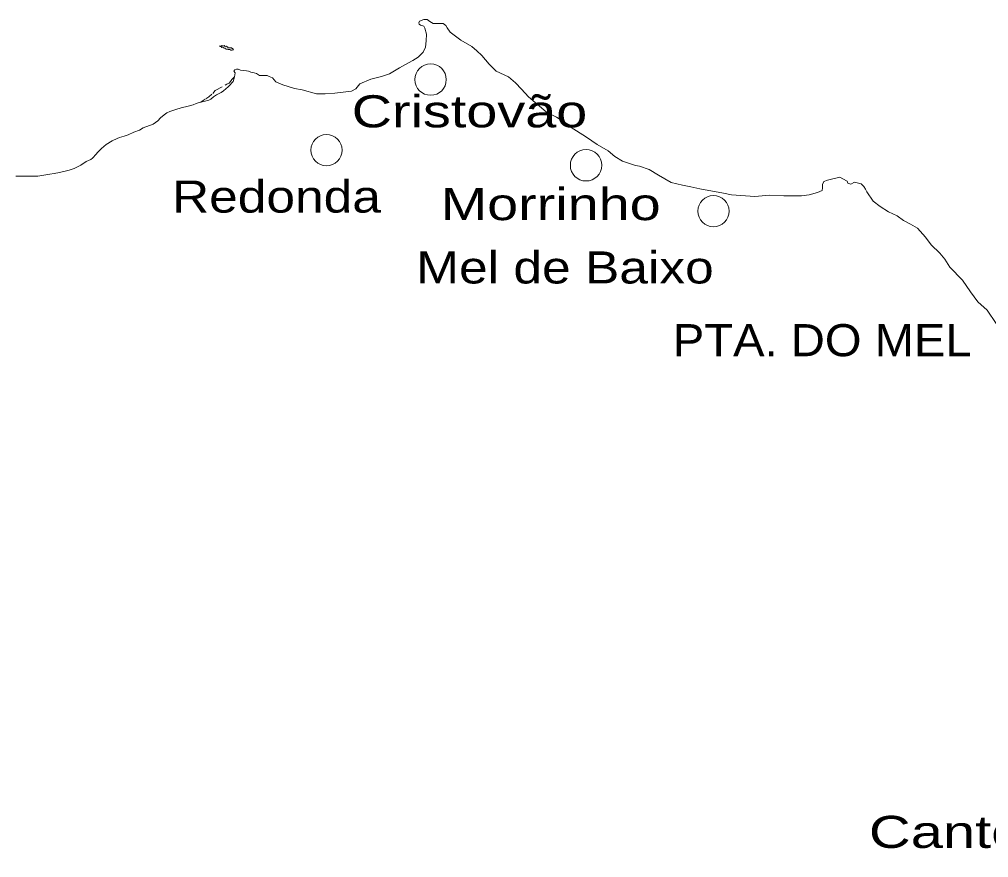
# Model space of a CAD drawing. Extents: x 47169 to 972804, y 7447977 to 9608469.
# Drawn here: x 717313 to 737887, y 9438119 to 9455908 of the extents above; entities that cross this region are included whole.
import ezdxf

# ---------------------------------------------------------------- set-up
doc = ezdxf.new("R2010")
doc.units = 0
doc.header["$LTSCALE"] = 270
doc.linetypes.add('DOTTED', pattern=[1.5, 0.3, -1.2])
doc.layers.add('1', color=7, linetype='Continuous', lineweight=13)
doc.layers.add('2', color=7, linetype='Continuous', lineweight=13)
doc.layers.add('3', color=7, linetype='Continuous')

msp = doc.modelspace()

# ---------------------------------------------------------------- linework, layer by layer
at = {"layer": '1'}
for points in [[(736954.5, 9450817.2), (736852.8, 9450945.9), (736668.1, 9451125.7), (736547.7, 9451287.6), (736376.4, 9451478.4), (736230.2, 9451561.8), (736079.6, 9451639.7), (735946.8, 9451740.8), (735762.9, 9451823.2), (735582.4, 9451936.7), (735434.1, 9452047.8), (735300.5, 9452246.2), (735275.1, 9452301.6), (735240.9, 9452358.1), (735182.3, 9452415.8), (735039.3, 9452450.5), (734963.7, 9452407.6), (734901.7, 9452432.2), (734886.3, 9452475.4), (734874.1, 9452480.9), (734725.7, 9452558.8), (734465.9, 9452498.8), (734392.5, 9452464.8), (734360.2, 9452404), (734360, 9452335.5), (734357.6, 9452276.8), (734256.5, 9452235.1), (734075.5, 9452183.7), (733914.5, 9452164.3), (733729.2, 9452160.5), (733537.3, 9452162.2), (733234.5, 9452178.6), (732921.6, 9452148.7), (732429.1, 9452184.5), (732261.7, 9452221.5), (731759.4, 9452310.5), (731567.6, 9452352), (731391.3, 9452390.2), (731147.4, 9452449.6), (730881.7, 9452605.3), (730684.6, 9452722.1), (730475.1, 9452794.6), (730388.6, 9452803.7), (730116, 9452899.7), (729954.3, 9452995.3), (729809.4, 9453121.9), (729576.8, 9453253.1), (729352.1, 9453409.8), (729139.5, 9453545.4), (729027.7, 9453616.5), (728989, 9453669.8), (728838.4, 9453755.4), (728715.5, 9453831), (728493.9, 9453944.5), (728120, 9454265.3), (727971.8, 9454427.3), (727845.7, 9454561.5), (727697.5, 9454685.8), (727434.9, 9454811.6), (727286.7, 9454960.3), (727127.5, 9455141.1), (727022.4, 9455239.9), (726915.1, 9455333.1), (726682.5, 9455468.8), (726460, 9455635.4), (726393.7, 9455727.4), (726366.2, 9455778.3), (726309.7, 9455818.3), (726189.9, 9455817.6), (726093.4, 9455820.1), (726029.2, 9455862.3), (725967.2, 9455907.9), (725896.2, 9455908.1), (725809.5, 9455871.8), (725789.4, 9455833.2), (725800.4, 9455805.5), (725828.1, 9455785.5), (725896.8, 9455767.6), (725922.2, 9455724.4), (725951.8, 9455594.9), (725951.3, 9455452.2), (725934.3, 9455315.1), (725881.8, 9455210.2), (725775, 9455109.8), (725668.3, 9455038.3), (725492.7, 9454940.4), (725381.6, 9454876.6), (725172.6, 9454755.5), (725002.7, 9454698.5), (724770.7, 9454636.2), (724541.8, 9454537.3), (724458.3, 9454435.8), (724361.7, 9454384.1), (724007.6, 9454338.8), (723806.8, 9454327.2), (723620.4, 9454328.9), (723317.8, 9454416.1), (723153.7, 9454443.1), (722904.3, 9454515.7), (722753.6, 9454581.5), (722682.9, 9454667.9)], [(722413.5, 9454720.7), (722370.3, 9454748.5), (722343.7, 9454761.9), (722298.2, 9454773.1), (722229.5, 9454791), (722175.2, 9454812.2), (722130.8, 9454815.6), (722069.8, 9454822.4), (722007.8, 9454833.7), (721957.9, 9454853.7), (721922.4, 9454854.9), (721885.7, 9454837.4), (721862.3, 9454807.6), (721892.2, 9454775.4), (721877.5, 9454685.8), (721852.8, 9454590.8), (721817.2, 9454552.2), (721794.9, 9454524.6), (721744.9, 9454473.9), (721647, 9454390.1), (721593.6, 9454353.8), (721499.2, 9454307.6), (721436.9, 9454261.3), (721374.7, 9454215.1), (721333.6, 9454193.1), (721231.4, 9454162.4), (721165.9, 9454152.7), (721104.9, 9454137.3), (721067.1, 9454122), (721001.5, 9454092.3), (720922.7, 9454070.4), (720842.8, 9454054.1), (720770.6, 9454035.5), (720610.7, 9453990.6), (720508.6, 9453953.3), (720441.9, 9453922.5), (720387.4, 9453881.8), (720309.6, 9453815.7), (720255.1, 9453756.1), (720155, 9453687.8), (719941.8, 9453603.3), (719864, 9453559.3), (719745.1, 9453516.5), (719624, 9453461.5), (719538.5, 9453429.7), (719438.6, 9453403.5), (719388.6, 9453378.2), (719283.1, 9453327.6), (719154.2, 9453252.8), (719057.4, 9453166.8), (718972.9, 9453085.2), (718942.8, 9453047.7), (718863.8, 9452962.8), (718831.5, 9452934.1), (718731.5, 9452889), (718616, 9452817.5), (718474.9, 9452746), (718367.1, 9452705.4), (718162.9, 9452656.2), (718054.1, 9452634.4), (717958.6, 9452620.3), (717707.8, 9452583.5), (717580.2, 9452579.4), (717451.6, 9452579.8), (717236.3, 9452581.6)], [(722682.9, 9454667.9), (722612, 9454696.9), (722573.2, 9454720.3), (722513.3, 9454720.4), (722462.3, 9454719.5), (722413.5, 9454720.7)], [(738046.2, 9449450.9), (737854.1, 9449734.7), (737657.2, 9449914.5), (737500.3, 9450127.4), (737335.8, 9450375.7), (737062.7, 9450652.1), (736954.5, 9450817.2)]]:
    msp.add_lwpolyline(points, dxfattribs=at)
msp.add_lwpolyline([(721788.4, 9455305.5), (721809.5, 9455305.5), (721821.7, 9455304.3), (721825, 9455292.1), (721840.5, 9455291), (721853.8, 9455278.8), (721856, 9455262.2), (721830.4, 9455255.6), (721804.9, 9455257.9), (721783.9, 9455269), (721747.2, 9455265.8), (721729.5, 9455278.1), (721698.5, 9455278.1), (721687.4, 9455299.2), (721655.3, 9455300.4), (721643.1, 9455318.1), (721607.6, 9455312.7), (721597.7, 9455330.4), (721571, 9455330.5), (721571.1, 9455346), (721585.5, 9455341.5), (721611.1, 9455355.8), (721634.3, 9455340.3), (721662.1, 9455352.4), (721683.1, 9455331.3), (721699.7, 9455336.8), (721735.2, 9455321.2), (721740.7, 9455305.7), (721766.2, 9455303.4)], close=True, dxfattribs=at)
at = {"layer": '1', "linetype": 'DOTTED'}
msp.add_lwpolyline([(721165.9, 9454152.7), (721191.5, 9454169.2), (721271.5, 9454219.8), (721332.7, 9454267.2), (721417.2, 9454336.6), (721471.7, 9454397.3), (721549.5, 9454439.1), (721678.4, 9454509.5), (721719.5, 9454533.7), (721767.3, 9454554.6), (721797.3, 9454589.9), (721824.1, 9454632.9), (721836.3, 9454647.3), (721877.5, 9454685.8)], dxfattribs=at)
at = {"layer": '2'}
for centre, radius in [((726042, 9454630.1), 332.8), ((723832, 9453133.7), 332.3), ((729341.3, 9452811.4), 332.9), ((732046.4, 9451838.4), 332.8)]:
    msp.add_circle(centre, radius, dxfattribs=at)

# ---------------------------------------------------------------- texts
at = {"layer": '3'}
for s, height, width, p in [('Cristovão', 680.9, 1.3, (724368.2, 9453616.5)), ('Redonda', 680.9, 1.2, (720552.3, 9451807.7)), ('Morrinho', 680.9, 1.3, (726255.9, 9451647.4)), ('Mel de Baixo', 680.9, 1.2, (725735.9, 9450303.1)), ('PTA. DO MEL', 680.9, 1.1, (731183.2, 9448759.7)), ('Canto do Mangue', 680.8, 1.35, (735346.1, 9438323.9))]:
    msp.add_text(s, height=height, dxfattribs=dict(at, width=width)).set_placement(p)

doc.saveas('drawing.dxf')
